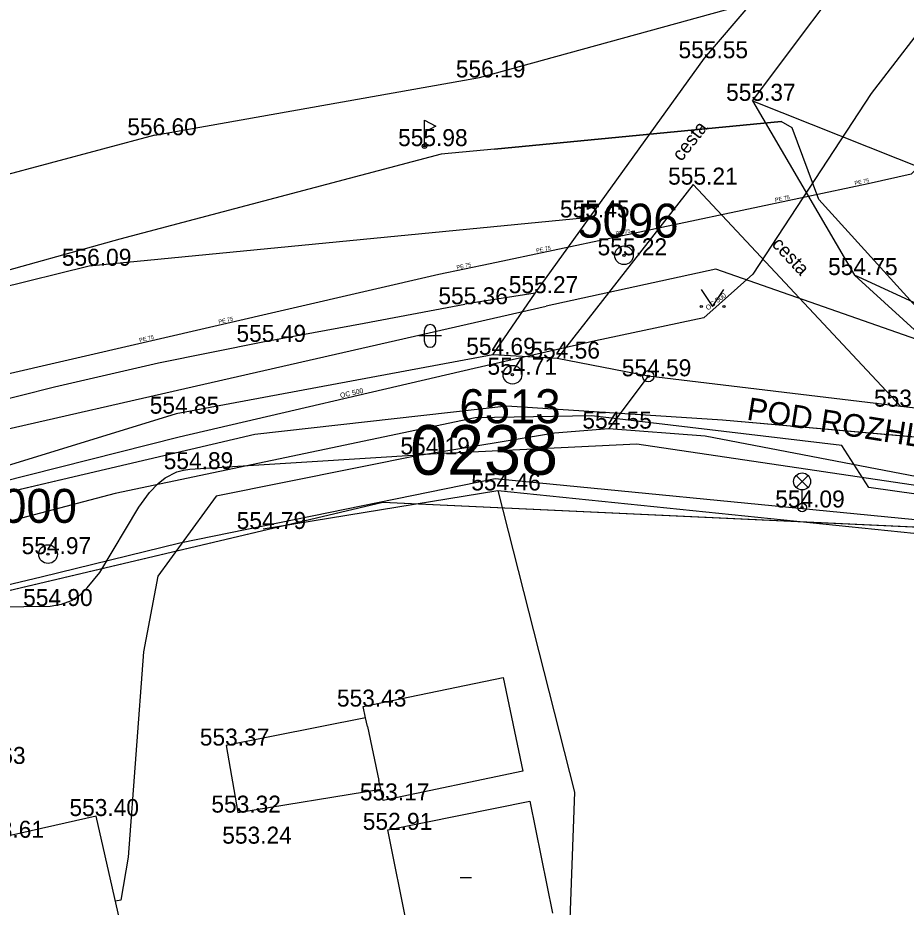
# Model space of a CAD drawing. Extents: x -669393 to -668650, y -1126925 to -1126294.
# Drawn here: x -669019.8 to -668980.61, y -1126507.85 to -1126468.58 of the extents above; entities that cross this region are included whole.
import ezdxf

# ---------------------------------------------------------------- set-up
doc = ezdxf.new("R2010")
doc.units = 0
for name, color, linetype in [('G_Bod_tecka', 7, 'Continuous'), ('G_Bod_vyska', 7, 'Continuous'), ('G_Bodove_pole', 7, 'Continuous'), ('G_Breh_Teren', 7, 'Continuous'), ('G_Budovy-znacky', 7, 'Continuous'), ('G_Budovy_Objekty', 7, 'Continuous'), ('G_Budovy_vstupy', 7, 'Continuous'), ('G_Cesty_Schody', 7, 'Continuous'), ('G_Objekty_technicke', 7, 'Continuous'), ('G_Plochy_zpevnene', 7, 'Continuous'), ('G_Ploty', 7, 'Continuous'), ('G_Popisy_Nazvy', 7, 'Continuous'), ('G_Popisy_povrchu', 7, 'Continuous'), ('G_Site-Sloupy', 7, 'Continuous'), ('G_Z_CHRANICKA-TEPLOVOD_kotovane', 7, 'Continuous'), ('G_Z_ELsilove_podz_kotovane', 7, 'Continuous'), ('G_Z_PLYNY_podz_geodeticky', 7, 'Continuous'), ('G_Z_PLYNY_podz_priblizne', 7, 'Continuous'), ('G_Z_SPOJE_podz_geodeticky', 7, 'Continuous'), ('G_Z_SPOJE_podz_kotovane', 7, 'Continuous'), ('G_Z_SPOJE_podz_priblizne', 7, 'Continuous'), ('G_Z_SPOJE_podz_zahozene', 7, 'Continuous'), ('G_Z_VODA_podz_kotovane', 7, 'Continuous'), ('G_Zelen-rozhrani', 7, 'Continuous'), ('G_Zelen-Znacky', 7, 'Continuous'), ('Vrstva 1', 7, 'Continuous'), ('Vrstva 11', 7, 'Continuous'), ('Vrstva 26', 7, 'Continuous'), ('Vrstva 4', 7, 'Continuous'), ('Vrstva 62', 7, 'Continuous')]:
    doc.layers.add(name, color=color, linetype=linetype)

msp = doc.modelspace()

# ---------------------------------------------------------------- linework, layer by layer
at = {"layer": 'G_Bod_tecka'}
for p, q in [((-668989.5, -1126470.37), (-668989.5, -1126470.37)), ((-668999.44, -1126471.22), (-668999.44, -1126471.22)), ((-668987.39, -1126472.25), (-668987.39, -1126472.25)), ((-669013.76, -1126473.77), (-669013.76, -1126473.77)), ((-669001.86, -1126474.25), (-669001.86, -1126474.25)), ((-668990.01, -1126475.95), (-668990.01, -1126475.95)), ((-668994.72, -1126477.4), (-668994.72, -1126477.4)), ((-668993.06, -1126479.07), (-668993.06, -1126479.07)), ((-669016.66, -1126479.53), (-669016.66, -1126479.53)), ((-668982.89, -1126479.94), (-668982.89, -1126479.94)), ((-668996.98, -1126480.74), (-668996.98, -1126480.74)), ((-669000.08, -1126481.23), (-669000.08, -1126481.23)), ((-669008.99, -1126482.89), (-669008.99, -1126482.89)), ((-668998.84, -1126483.46), (-668998.84, -1126483.46)), ((-668996.01, -1126483.63), (-668996.01, -1126483.63)), ((-668997.98, -1126484.34), (-668997.98, -1126484.34)), ((-668991.99, -1126484.41), (-668991.99, -1126484.41)), ((-668980.85, -1126485.75), (-668980.85, -1126485.75)), ((-669012.82, -1126486.06), (-669012.82, -1126486.06)), ((-668993.73, -1126486.72), (-668993.73, -1126486.72)), ((-669001.9, -1126487.86), (-669001.9, -1126487.86)), ((-669012.21, -1126488.51), (-669012.21, -1126488.51)), ((-668998.62, -1126489.45), (-668998.62, -1126489.45)), ((-668985.2, -1126490.2), (-668985.2, -1126490.2)), ((-669008.98, -1126491.15), (-669008.98, -1126491.15)), ((-669018.47, -1126492.26), (-669018.47, -1126492.26)), ((-669018.38, -1126494.55), (-669018.38, -1126494.55)), ((-669004.56, -1126498.99), (-669004.56, -1126498.99)), ((-669010.61, -1126500.71), (-669010.61, -1126500.71)), ((-669003.69, -1126503.13), (-669003.69, -1126503.13)), ((-669016.34, -1126503.82), (-669016.34, -1126503.82)), ((-669010.1, -1126503.67), (-669010.1, -1126503.67)), ((-669003.48, -1126504.43), (-669003.48, -1126504.43)), ((-669009.63, -1126505.04), (-669009.63, -1126505.04))]:
    msp.add_line(p, q, dxfattribs=at)
at = {"layer": 'G_Bodove_pole'}
for centre, radius in [((-668993.06, -1126479.07), 0.412), ((-668993.06, -1126479.07), 0.05), ((-668997.98, -1126484.34), 0.412), ((-668997.98, -1126484.34), 0.05), ((-669018.47, -1126492.26), 0.412), ((-669018.47, -1126492.26), 0.05)]:
    msp.add_circle(centre, radius, dxfattribs=at)
at = {"layer": 'G_Breh_Teren'}
for p, q in [((-668987.39, -1126472.25), (-668977.26, -1126476.28)), ((-668976.78, -1126482.76), (-668982.89, -1126479.94)), ((-668996.98, -1126480.74), (-669000.08, -1126481.23))]:
    msp.add_line(p, q, dxfattribs=at)
at = {"layer": 'G_Budovy-znacky'}
msp.add_line((-669000.28, -1126506.53), (-668999.78, -1126506.53), dxfattribs=at)
at = {"layer": 'G_Budovy_Objekty'}
for p, q in [((-669004.56, -1126498.99), (-668998.39, -1126497.7)), ((-668998.39, -1126497.7), (-668997.52, -1126501.84)), ((-669004.46, -1126499.48), (-669004.56, -1126498.99)), ((-669004.38, -1126499.87), (-669004.46, -1126499.48)), ((-668997.52, -1126501.84), (-669003.69, -1126503.13)), ((-669003.79, -1126502.64), (-669003.88, -1126502.25)), ((-669003.69, -1126503.13), (-669003.79, -1126502.64)), ((-669003.48, -1126504.43), (-668997.21, -1126503.16)), ((-668997.21, -1126503.16), (-668996.21, -1126508.11)), ((-669016.34, -1126503.82), (-669020.6, -1126504.78)), ((-669014.56, -1126511.7), (-669016.34, -1126503.82)), ((-669002.48, -1126509.38), (-669003.48, -1126504.43))]:
    msp.add_line(p, q, dxfattribs=at)
at = {"layer": 'G_Budovy_vstupy'}
msp.add_line((-669004.38, -1126499.87), (-669003.88, -1126502.25), dxfattribs=at)
at = {"layer": 'G_Cesty_Schody'}
for p, q in [((-668989.5, -1126470.37), (-668987.4, -1126467.91)), ((-668996.98, -1126480.74), (-668989.5, -1126470.37)), ((-668990.01, -1126475.95), (-668996.01, -1126483.63)), ((-668980.85, -1126485.75), (-668990.01, -1126475.95)), ((-668998.84, -1126483.46), (-668996.98, -1126480.74)), ((-668998.84, -1126483.46), (-669012.82, -1126486.06)), ((-668996.01, -1126483.63), (-668998.84, -1126483.46)), ((-668991.99, -1126484.41), (-668996.01, -1126483.63)), ((-669012.82, -1126486.06), (-669040.81, -1126494.68))]:
    msp.add_line(p, q, dxfattribs=at)
for points in [[(-668987.39, -1126472.25), (-668982.11, -1126465.21), (-668976.82, -1126458.17), (-668974.68, -1126455.18), (-668971.59, -1126450.6), (-668970.01, -1126448.32), (-668968.35, -1126446.06), (-668967.69, -1126445.28), (-668967.05, -1126444.67), (-668966.44, -1126444.17), (-668965.31, -1126443.41), (-668964.4, -1126442.92), (-668963.69, -1126442.59), (-668962.6, -1126442.18), (-668961.48, -1126441.85), (-668960.45, -1126441.61), (-668958.64, -1126441.32), (-668957.27, -1126441.2), (-668956.25, -1126441.17), (-668954.72, -1126441.24), (-668953.21, -1126441.42), (-668944.59, -1126442.87), (-668935.98, -1126444.4), (-668920.75, -1126448.74)], [(-668987.39, -1126472.25), (-668982.89, -1126479.94), (-668975.95, -1126486.28)], [(-669110.21, -1126508.54), (-669102.79, -1126507.21), (-669099.08, -1126506.51), (-669095.39, -1126505.73), (-669087.27, -1126503.88), (-669081.18, -1126502.46), (-669072.08, -1126500.22), (-669067.55, -1126499.05), (-669063.02, -1126497.84), (-669059.85, -1126496.94), (-669054.34, -1126495.28), (-669046.1, -1126492.68), (-669041.96, -1126491.41), (-669037.82, -1126490.21), (-669030.65, -1126488.19), (-669025.27, -1126486.7), (-669021.23, -1126485.64), (-669018.18, -1126484.88), (-669013.6, -1126483.82), (-669008.99, -1126482.89), (-669004.53, -1126482.06), (-669000.08, -1126481.23)], [(-669001.9, -1126487.86), (-668996.12, -1126486.9), (-668993.73, -1126486.72)], [(-669023.06, -1126494.63), (-669020.72, -1126494.59), (-669018.38, -1126494.55), (-669017.87, -1126494.47), (-669017.43, -1126494.3), (-669017.06, -1126494.05), (-669016.74, -1126493.75), (-669016.19, -1126493.07), (-669014.47, -1126490.18), (-669014, -1126489.54), (-669013.61, -1126489.14), (-669013.3, -1126488.89), (-669012.79, -1126488.63), (-669012.5, -1126488.55), (-669012.21, -1126488.51), (-669007.05, -1126488.18), (-669001.9, -1126487.86)]]:
    msp.add_lwpolyline(points, dxfattribs=at)
at = {"layer": 'G_Objekty_technicke'}
for p, q in [((-668985.465, -1126488.785), (-668984.935, -1126489.315)), ((-668985.465, -1126489.315), (-668984.935, -1126488.785)), ((-668985.2, -1126490.2), (-668985.2, -1126489.425))]:
    msp.add_line(p, q, dxfattribs=at)
for centre, radius in [((-668985.2, -1126489.05), 0.375), ((-668985.2, -1126490.2), 0.19), ((-668985.2, -1126490.2), 0.05)]:
    msp.add_circle(centre, radius, dxfattribs=at)
at = {"layer": 'G_Plochy_zpevnene'}
for p, q in [((-668991.99, -1126484.41), (-668993.73, -1126486.72)), ((-668980.85, -1126485.75), (-668991.99, -1126484.41)), ((-668975.95, -1126486.28), (-668980.85, -1126485.75)), ((-669004.46, -1126499.48), (-669010.61, -1126500.71)), ((-669010.61, -1126500.71), (-669010.1, -1126503.67)), ((-669010.1, -1126503.67), (-669003.79, -1126502.64))]:
    msp.add_line(p, q, dxfattribs=at)
msp.add_lwpolyline([(-668993.73, -1126486.72), (-668989.48, -1126487.04), (-668974.38, -1126489.94)], dxfattribs=at)
at = {"layer": 'G_Ploty'}
for p, q in [((-669008.98, -1126491.15), (-668998.62, -1126489.45)), ((-668998.62, -1126489.45), (-668965.26, -1126492.89))]:
    msp.add_line(p, q, dxfattribs=at)
msp.add_lwpolyline([(-668998.62, -1126489.45), (-668995.25, -1126502.77), (-668995.61, -1126512.79)], dxfattribs=at)
at = {"layer": 'G_Site-Sloupy'}
for p, q in [((-669001.86, -1126474.25), (-669001.86, -1126473.1)), ((-669001.86, -1126473.1), (-669001.36, -1126473.365)), ((-669001.36, -1126473.365), (-669001.86, -1126473.63))]:
    msp.add_line(p, q, dxfattribs=at)
for centre, radius in [((-669001.86, -1126474.25), 0.1), ((-669001.86, -1126474.25), 0.0348), ((-668991.99, -1126484.41), 0.25), ((-668991.99, -1126484.41), 0.05)]:
    msp.add_circle(centre, radius, dxfattribs=at)
at = {"layer": 'G_Z_CHRANICKA-TEPLOVOD_kotovane'}
msp.add_lwpolyline([(-668998.77, -1126474.38), (-668986.13, -1126473.17)], dxfattribs=at)
at = {"layer": 'G_Z_ELsilove_podz_kotovane'}
msp.add_lwpolyline([(-669072.67, -1126506.76), (-669039.7, -1126498.47), (-669003.7, -1126489.96), (-668970.42, -1126491.51)], dxfattribs=at)
at = {"layer": 'G_Z_PLYNY_podz_geodeticky'}
msp.add_lwpolyline([(-668915.1, -1126503.98), (-668916.95, -1126503.34), (-668922.64, -1126500.94), (-668926.46, -1126499.78), (-668938.01, -1126496.28), (-668944.43, -1126494.34), (-668959.79, -1126489.68), (-668964.08, -1126488.41), (-668969.46, -1126486.53), (-668989, -1126479.68), (-668996.49, -1126481.32)], dxfattribs=at)
at = {"layer": 'G_Z_PLYNY_podz_priblizne'}
msp.add_lwpolyline([(-669181.88, -1126524.23), (-669116.84, -1126508.75), (-669115.579, -1126508.147), (-669115.45, -1126508.118), (-669036.41, -1126490.42), (-669012.438, -1126484.955), (-668996.49, -1126481.32)], dxfattribs=at)
at = {"layer": 'G_Z_SPOJE_podz_geodeticky'}
for points in [[(-668954.5, -1126468.94), (-668956.68, -1126473.32), (-668963.52, -1126487.02), (-668965.6, -1126492.17), (-668998.75, -1126488.93), (-669012.65, -1126491.77), (-669018.78, -1126493.27), (-669035.34, -1126497.22), (-669051.6, -1126501.03), (-669100.76, -1126512.78), (-669114.65, -1126516.02), (-669131.97, -1126520.55), (-669160.13, -1126526.57), (-669163.02, -1126527.37)], [(-668931.13, -1126506.48), (-668932.61, -1126504.61), (-668935.84, -1126502.84), (-668943.19, -1126499.83), (-668955.91, -1126495.57), (-668966.94, -1126491.53), (-668976.02, -1126489.85), (-668992.49, -1126487.4), (-669001.9, -1126487.86), (-669011.05, -1126489.7), (-669013.63, -1126493.23), (-669014.26, -1126496.57), (-669014.93, -1126505.63), (-669015.26, -1126507.53), (-669015.5, -1126507.58)]]:
    msp.add_lwpolyline(points, dxfattribs=at)
at = {"layer": 'G_Z_SPOJE_podz_kotovane'}
for points in [[(-668964.18, -1126494.73), (-668963.87, -1126492.97), (-668963.49, -1126488.98), (-668977.14, -1126484.68), (-668984.47, -1126476.61), (-668985.64, -1126473.44), (-668986.13, -1126473.17), (-668998.77, -1126474.38), (-669001.12, -1126474.61), (-669015.3, -1126478.36), (-669033.98, -1126483.56), (-669053.22, -1126487.91), (-669089.92, -1126495.07), (-669104.26, -1126498.47), (-669118, -1126502.49)], [(-668969, -1126491.19), (-668982.26, -1126489.32), (-668983.45, -1126487.46), (-668994.48, -1126486.15), (-668999.63, -1126486.24), (-669015.51, -1126489.58), (-669021.84, -1126491.24), (-669025.69, -1126492.14), (-669028.64, -1126493.15), (-669034.66, -1126495.13), (-669040.08, -1126496.55), (-669044.41, -1126497.51), (-669048.66, -1126498.89), (-669050.9, -1126499.16), (-669059.48, -1126501.74), (-669060.92, -1126502.31), (-669079.66, -1126506.88), (-669101.24, -1126512.21), (-669118.15, -1126516.32)], [(-668931.13, -1126506.48), (-668932.61, -1126504.61), (-668935.84, -1126502.84), (-668943.19, -1126499.83), (-668955.91, -1126495.57), (-668966.94, -1126491.53), (-668976.02, -1126489.85), (-668992.49, -1126487.4), (-669001.9, -1126487.86), (-669011.05, -1126489.7), (-669013.63, -1126493.23), (-669014.26, -1126496.57), (-669014.93, -1126505.63), (-669015.26, -1126507.53), (-669015.5, -1126507.58)]]:
    msp.add_lwpolyline(points, dxfattribs=at)
at = {"layer": 'G_Z_SPOJE_podz_priblizne'}
for points in [[(-668954.5, -1126468.94), (-668956.68, -1126473.32), (-668963.52, -1126487.02), (-668965.6, -1126492.17), (-668998.75, -1126488.93), (-669012.65, -1126491.77), (-669018.78, -1126493.27), (-669035.34, -1126497.22), (-669051.6, -1126501.03), (-669100.76, -1126512.78), (-669114.65, -1126516.02), (-669131.97, -1126520.55), (-669160.13, -1126526.57), (-669163.02, -1126527.37)], [(-668931.13, -1126506.48), (-668932.61, -1126504.61), (-668935.84, -1126502.84), (-668943.19, -1126499.83), (-668955.91, -1126495.57), (-668966.94, -1126491.53), (-668976.02, -1126489.85), (-668992.49, -1126487.4), (-669001.9, -1126487.86), (-669011.05, -1126489.7), (-669013.63, -1126493.23), (-669014.26, -1126496.57), (-669014.93, -1126505.63), (-669015.26, -1126507.53), (-669015.5, -1126507.58)]]:
    msp.add_lwpolyline(points, dxfattribs=at)
at = {"layer": 'G_Z_SPOJE_podz_zahozene'}
for p, q in [((-669009.35, -1126486.96), (-668998.23, -1126485.72)), ((-668998.23, -1126485.72), (-668988.71, -1126486.33)), ((-668988.71, -1126486.33), (-668964.64, -1126488.47)), ((-669017.82, -1126488.95), (-669009.35, -1126486.96)), ((-669025.15, -1126490.67), (-669017.82, -1126488.95))]:
    msp.add_line(p, q, dxfattribs=at)
at = {"layer": 'G_Z_VODA_podz_kotovane'}
for p, q in [((-668982.29, -1126475.91), (-668998.96, -1126479.45)), ((-668998.96, -1126479.45), (-669001.23, -1126479.92)), ((-669001.23, -1126479.92), (-669100.81, -1126502.89))]:
    msp.add_line(p, q, dxfattribs=at)
for points in [[(-668976.13, -1126464.08), (-668982.15, -1126471.93), (-668987.37, -1126479.9), (-668989.54, -1126481.83), (-668994.31, -1126482.84), (-668999.67, -1126484.06), (-669012.69, -1126487.09), (-669025.9, -1126490.43), (-669026.29, -1126490.54), (-669040.55, -1126494.53), (-669053.43, -1126498), (-669057.92, -1126499.31), (-669058.76, -1126500.33), (-669058.72, -1126501.93), (-669058.3, -1126504.32), (-669057.46, -1126511.36), (-669055.21, -1126521.72), (-669052.52, -1126536.84), (-669048.66, -1126559.56), (-669047.02, -1126570.09)], [(-668979.04, -1126474.18), (-668980.39, -1126475.49), (-668982.29, -1126475.91)]]:
    msp.add_lwpolyline(points, dxfattribs=at)
at = {"layer": 'G_Zelen-rozhrani'}
for p, q in [((-668999.44, -1126471.22), (-668987.4, -1126467.91)), ((-669013.76, -1126473.77), (-668999.44, -1126471.22)), ((-669013.76, -1126473.77), (-669065.11, -1126487.43)), ((-669016.66, -1126479.53), (-668994.72, -1126477.4)), ((-669064.34, -1126491.39), (-669016.66, -1126479.53))]:
    msp.add_line(p, q, dxfattribs=at)
at = {"layer": 'G_Zelen-Znacky'}
for p, q in [((-668989.65, -1126480.58), (-668989.15, -1126481.33)), ((-668989.15, -1126481.33), (-668988.65, -1126480.58)), ((-669001.86, -1126482.88), (-669001.86, -1126482.38)), ((-669001.36, -1126482.88), (-669001.36, -1126482.38)), ((-669001.11, -1126482.63), (-669002.11, -1126482.63))]:
    msp.add_line(p, q, dxfattribs=at)
for centre in [(-668989.65, -1126481.33), (-668988.65, -1126481.33)]:
    msp.add_circle(centre, 0.05, dxfattribs=at)
for centre, start, end in [((-669001.61, -1126482.38), 0, 180), ((-669001.61, -1126482.88), 180, 0)]:
    msp.add_arc(centre, 0.25, start, end, dxfattribs=at)
at = {"layer": 'Vrstva 1'}
msp.add_line((-669003.7, -1126489.96), (-669003.7, -1126489.96), dxfattribs=at)
at = {"layer": 'Vrstva 11'}
msp.add_lwpolyline([(-669158.05, -1126523.476), (-669081.405, -1126505.472), (-669075.765, -1126504.577), (-669070.29, -1126503.55), (-669065.419, -1126502.297), (-669060.653, -1126500.848), (-669050.065, -1126497.814), (-669036.38, -1126493.893), (-669025.147, -1126490.674), (-669017.819, -1126488.951), (-669009.352, -1126486.961), (-668998.225, -1126485.721), (-668988.712, -1126486.333), (-668964.641, -1126488.467), (-668965.183, -1126492.339), (-668964.91, -1126492.753), (-668953.167, -1126497.038), (-668943.176, -1126500.435), (-668935.317, -1126503.821), (-668934.705, -1126502.904), (-668931.263, -1126505.201), (-668929.184, -1126506.851), (-668928.464, -1126509.545)], dxfattribs=at)
at = {"layer": 'Vrstva 26'}
for p, q in [((-668982.29, -1126475.91), (-668998.96, -1126479.45)), ((-668998.96, -1126479.45), (-669001.23, -1126479.92)), ((-669001.23, -1126479.92), (-669100.81, -1126502.89))]:
    msp.add_line(p, q, dxfattribs=at)
for points in [[(-668976.13, -1126464.08), (-668982.15, -1126471.93), (-668987.37, -1126479.9), (-668989.54, -1126481.83), (-668994.31, -1126482.84), (-668999.67, -1126484.06), (-669012.69, -1126487.09), (-669025.9, -1126490.43), (-669026.294, -1126490.54), (-669040.55, -1126494.53), (-669053.43, -1126498), (-669057.92, -1126499.31), (-669058.76, -1126500.33), (-669058.72, -1126501.93), (-669058.3, -1126504.32), (-669057.46, -1126511.36), (-669055.21, -1126521.72), (-669052.52, -1126536.84), (-669048.66, -1126559.56), (-669047.02, -1126570.09)], [(-668979.04, -1126474.18), (-668980.39, -1126475.49), (-668982.29, -1126475.91)]]:
    msp.add_lwpolyline(points, dxfattribs=at)
at = {"layer": 'Vrstva 62'}
for p, q in [((-669039.7, -1126498.47), (-669003.7, -1126489.96)), ((-669003.7, -1126489.96), (-668970.42, -1126491.51))]:
    msp.add_line(p, q, dxfattribs=at)

# ---------------------------------------------------------------- texts
at = {"layer": 'G_Bod_vyska'}
for s, p in [('555.55', (-668990.654, -1126470.37)), ('556.19', (-669000.478, -1126471.22)), ('555.37', (-668988.554, -1126472.25)), ('556.60', (-669014.973, -1126473.77)), ('555.98', (-669003.026, -1126474.25)), ('555.21', (-668991.112, -1126475.95)), ('555.45', (-668995.884, -1126477.4)), ('555.22', (-668994.224, -1126479.07)), ('556.09', (-669017.861, -1126479.53)), ('554.75', (-668984.054, -1126479.94)), ('555.27', (-668998.144, -1126480.74)), ('555.36', (-669001.248, -1126481.23)), ('555.49', (-669010.156, -1126482.89)), ('554.69', (-669000.02, -1126483.46)), ('554.56', (-668997.188, -1126483.63)), ('554.71', (-668999.082, -1126484.34)), ('554.59', (-668993.156, -1126484.41)), ('553.86', (-668982.028, -1126485.75)), ('554.85', (-669013.984, -1126486.06)), ('554.55', (-668994.894, -1126486.72)), ('554.19', (-669002.924, -1126487.86)), ('554.89', (-669013.366, -1126488.51)), ('554.46', (-668999.798, -1126489.45)), ('554.09', (-668986.388, -1126490.2)), ('554.79', (-669010.146, -1126491.15)), ('554.97', (-669019.636, -1126492.26)), ('554.90', (-669019.568, -1126494.55)), ('553.43', (-669005.724, -1126498.99)), ('553.37', (-669011.774, -1126500.71)), ('553.63', (-669022.528, -1126501.52)), ('553.17', (-669004.712, -1126503.13)), ('553.40', (-669017.526, -1126503.82)), ('553.32', (-669011.264, -1126503.67)), ('552.91', (-669004.584, -1126504.43)), ('553.61', (-669021.716, -1126504.78)), ('553.24', (-669010.784, -1126505.04))]:
    msp.add_text(s, height=0.75, dxfattribs=at).set_placement(p)
at = {"layer": 'G_Bodove_pole'}
for s, p in [('5096', (-668995.115, -1126478.29)), ('6513', (-669000.319, -1126486.48)), ('8000', (-669021.657, -1126490.88))]:
    msp.add_text(s, height=1.5, dxfattribs=at).set_placement(p)
at = {"layer": 'G_Popisy_Nazvy'}
msp.add_text('POD ROZHLEDNOU', height=1, rotation=350.9146, dxfattribs=at).set_placement((-668987.678, -1126486.321))
at = {"layer": 'G_Popisy_povrchu'}
for rotation, p in [(51.9842, (-668990.522, -1126474.957)), (313.0811, (-668986.572, -1126478.608))]:
    msp.add_text('cesta', height=0.6, rotation=rotation, dxfattribs=at).set_placement(p)
at = {"layer": 'Vrstva 4'}
for s, height, rotation, p in [('PE 75', 0.1755, 11.9865, (-668982.869, -1126475.971)), ('PE 75', 0.1755, 11.9658, (-668986.381, -1126476.716)), ('PE 75', 0.1755, 11.9658, (-668993.404, -1126478.207)), ('PE 75', 0.1755, 11.9865, (-668996.917, -1126478.953)), ('PE 75', 0.1755, 11.6135, (-669000.429, -1126479.692)), ('OC 500', 0.2194, 38.0322, (-668989.354, -1126481.511)), ('PE 75', 0.1755, 13.0545, (-669010.929, -1126482.094)), ('PE 75', 0.1755, 13.0059, (-669014.427, -1126482.901)), ('OC 500', 0.2194, 12.9877, (-669005.559, -1126485.369))]:
    msp.add_text(s, height=height, rotation=rotation, dxfattribs=at).set_placement(p)
msp.add_text('0238', height=2.1939, dxfattribs=at).set_placement((-669002.496, -1126488.758))

doc.saveas('drawing.dxf')
